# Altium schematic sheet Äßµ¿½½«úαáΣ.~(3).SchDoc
size A4
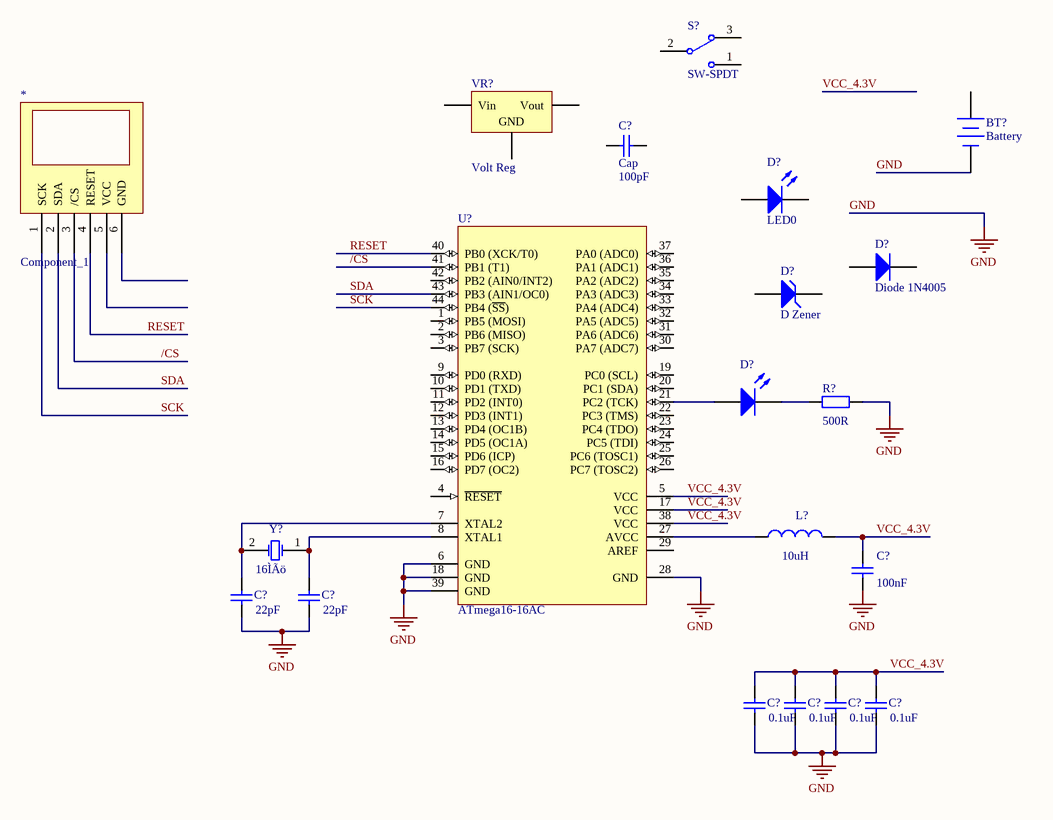
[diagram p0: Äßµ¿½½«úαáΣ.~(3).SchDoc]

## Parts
(Parts that share a designator on the sheet are numbered #1, #2 ... from top to bottom, then left to right.)
*  Component_1
BT?  Battery  [BAT-2]
C?#1  Cap  value 100pF  [RAD-0.3]
C?#2  value 100nF  [RAD-0.3]  (hidden comment: Cap)
C?#3  value 22pF  [RAD-0.3]  (hidden comment: Cap)
C?#4  value 22pF  [RAD-0.3]  (hidden comment: Cap)
C?#5  value 0.1uF  [RAD-0.3]  (hidden comment: Cap)
C?#6  value 0.1uF  [RAD-0.3]  (hidden comment: Cap)
C?#7  value 0.1uF  [RAD-0.3]  (hidden comment: Cap)
C?#8  value 0.1uF  [RAD-0.3]  (hidden comment: Cap)
D?#1  LED0  [LED-0]
D?#2  Diode 1N4005  [DIO10.46-5.3x2.8]
D?#3  D Zener  [DIODE-0.7]
D?#4  LED0  [LED-0]  (value not drawn)
L?  value 10uH  [INDC1005AL]  (hidden comment: Inductor)
R?  value 500R  [AXIAL-0.4]  (hidden comment: Res2)
S?  SW-SPDT  [TL36WW15050]
U?  ATmega16-16AC  [44A_N]
VR?  Volt Reg  [TO254P1510-3_4N]
Y?  16ÌÃö  [BCY-W2/D3.1]

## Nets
GND: BT?.2(-) C?#2.1 C?#3.1 C?#4.1 C?#5.1 C?#6.1 C?#7.1 C?#8.1 R?.2 U?.6(GND) U?.18(GND) U?.28(GND) U?.39(GND)
/CS: *.3(/CS) U?.41(PB1_(T1))
RESET: *.4(RESET) U?.40(PB0_(XCK/T0))
SCK: *.1(SCK) U?.44(PB4_(~{SS}))
SDA: *.2(SDA) U?.43(PB3_(AIN1/OC0))
VCC_4.3V: C?#2.2 C?#5.2 C?#6.2 C?#7.2 C?#8.2 L?.2 U?.5(VCC) U?.17(VCC) U?.38(VCC)
NetC?#3_2: C?#3.2 U?.7(XTAL2) Y?.2(OSC2)
NetC?#4_2: C?#4.2 U?.8(XTAL1) Y?.1(OSC1)
NetD?#4_1: D?#4.1(A) U?.21(PC2_(TCK))
NetD?#4_2: D?#4.2(K) R?.1
NetL?_1: L?.1 U?.27(AVCC)

Not connected (* = marked no-connect by the designer): * 5(VCC) 6(GND); BT? 1(+); C?#1 1 2; D?#1 1(A) 2(K); D?#2 1(A) 2(K); D?#3 1(A) 2(K); S? 1 2 3; U? 1(PB5_(MOSI)) 2(PB6_(MISO)) 3(PB7_(SCK)) 4(~{RESET}) 9(PD0_(RXD)) 10(PD1_(TXD)) 11(PD2_(INT0)) 12(PD3_(INT1)) 13(PD4_(OC1B)) 14(PD5_(OC1A)) 15(PD6_(ICP)) 16(PD7_(OC2)) 19(PC0_(SCL)) 20(PC1_(SDA)) 22(PC3_(TMS)) 23(PC4_(TDO)) 24(PC5_(TDI)) 25(PC6_(TOSC1)) 26(PC7_(TOSC2)) 29(AREF) 30(PA7_(ADC7)) 31(PA6_(ADC6)) 32(PA5_(ADC5)) 33(PA4_(ADC4)) 34(PA3_(ADC3)) 35(PA2_(ADC2)) 36(PA1_(ADC1)) 37(PA0_(ADC0)) 42(PB2_(AIN0/INT2)); VR? 1(Vin) 2(GND) 3(Vout)

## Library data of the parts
BT? = Battery: Multicell Battery
C?#1-C?#8 = Cap: Capacitor
D?#1 D?#4 = LED0: Typical INFRARED GaAs LED
D?#2 = Diode 1N4005: 1 Amp General Purpose Rectifier
D?#3 = D Zener: Zener Diode
L? = Inductor: Code_IEC: 1005
R? = Res2: Resistor
S? = SW-SPDT: SPDT Subminiature Toggle Switch, Right Angle Mounting, Vertical Actuation
U? = ATmega16-16AC: 8-Bit AVR Microcontroller with 16K Bytes of In-System Programmable Flash Memory
VR? = Volt Reg: Voltage Regulator
Y? = XTAL: Crystal Oscillator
